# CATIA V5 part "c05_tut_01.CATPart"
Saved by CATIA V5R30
Part number: Part1
Bounding box of the stored display mesh (mm): x -20 to 20, y 0 to 95, z 0 to 40
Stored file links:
  D:\PROJECTS\CATIA V56R 2020\Resources\c05_catia_v5_6r2020_tut\c05_tut_01.CATPart
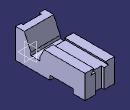
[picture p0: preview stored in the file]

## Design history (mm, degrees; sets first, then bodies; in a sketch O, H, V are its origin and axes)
Body1 (main body)
  Sketch1 on yz-plane, origin (0, 0, 0), H (0, 1, 0), V (0, 0, 1)
    line L1 (0, 0) -> (0, 40)
    line L2 (0, 40) -> (12, 40)
    point P2 (12, 40)
    line L3 (12, 40) -> (21, 20)
    point P3 (21, 20)
    line L4 (21, 20) -> (21, 16)
    line L5 (21, 16) -> (33, 16)
    line L6 (33, 16) -> (33, 20)
    point P6 (33, 20)
    line L7 (33, 20) -> (39, 32)
    point P7 (39, 32)
    line L8 (39, 32) -> (95, 32)
    line L9 (95, 32) -> (95, 0)
    line L10 (95, 0) -> (79, 0)
    line L11 (79, 0) -> (79, 6)
    line L12 (79, 6) -> (47, 6)
    line L13 (47, 6) -> (47, 0)
    point P13 (47, 0)
    line L14 (47, 0) -> (0, 0)
    distance L2 L14 = 40
    length L2 = 12
    distance L14 L5 = 16
    distance P3 L5 = 4
    distance L8 P6 = 12
    distance L12 L10 = 6
    distance L11 L9 = 16
    distance L13 L11 = 32
    distance P2 P7 H = 27
    distance L1 L9 = 95
    distance L8 L10 = 32
    distance P7 P6 H = 6
    length L5 = 12
    coincidence: P13 L10, L14 H
    vertical: L13 V, L1 V, L4 V, L6 V, L9 V, L11 V
    horizontal: L14 H, L10 H
  Pad1: profile Sketch1, direction (1, 0, 0), length 20, mirrored extent
  Sketch2 on face of Pad1 from Sketch1.L9, origin (0, 95, 0), H (-1, 0, 0), V (0, 0, 1)
    line L1 (-8, 32) -> (-12.0471, 26)
    line L2 (-12.0471, 26) -> (12.0471, 26)
    line L3 (12.0471, 26) -> (8, 32)
    line L4 (8, 32) -> (-8, 32)
    reference projected line E1 (20, 32) -> (-20, 32) from edge [face of Pad1 from Sketch1.L8 | face of Pad1 from Sketch1.L9]
    reference projected line E2 (20, 0) -> (-20, 0) from edge [face of Pad1 from Sketch1.L9 | face of Pad1 from Sketch1.L10]
    distance E2 L2 = 26
    angle L3 L2 = 56
    length L4 = 16
    horizontal: L2 H, L4 H
    coincidence: L4 E1
    symmetry: L1 L3 V
  Pocket1: profile Sketch2, direction (0, -1, 0), through (limit type 6)
  Sketch3 on face of Pad1 from Sketch1.L9, origin (0, 95, 0), H (-1, 0, 0), V (0, 0, 1)
    line L1 (-6, 26) -> (6, 26)
    line L2 (6, 26) -> (6, 0)
    line L3 (6, 0) -> (-6, 0)
    line L4 (-6, 0) -> (-6, 26)
    point P3 (6, 0)
    reference projected line E1 (-12.0471, 26) -> (12.0471, 26) from edge [face of Pad1 from Sketch1.L9 | face of Pocket1 from Sketch2.L2]
    distance L4 L2 = 12
    horizontal: L1 H, L3 H
    vertical: L2 V, L4 V
    coincidence: P3 H, L1 E1
    symmetry: L4 L2 V
  Pocket2: profile Sketch3, direction (0, -1, 0), length 4
  Sketch4 on face of Pad1 from Sketch1.L1, origin (0, 0, 0), H (1, 0, 0), V (0, 0, 1)
    point P1 (-12.5, 0)
    line L1 (-12.5, 0) -> (12.5, 0)
    line L2 (12.5, 0) -> (12.5, 40)
    line L3 (12.5, 40) -> (-12.5, 40)
    line L4 (-12.5, 40) -> (-12.5, 0)
    reference projected line E1 (-20, 40) -> (20, 40) from edge [face of Pad1 from Sketch1.L1 | face of Pad1 from Sketch1.L2]
    distance L4 L2 = 25
    coincidence: P1 H, L3 E1
    horizontal: L1 H, L3 H
    vertical: L2 V, L4 V
    symmetry: L4 L2 V
  Pocket3: profile Sketch4, direction (0, 1, 0), length 3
